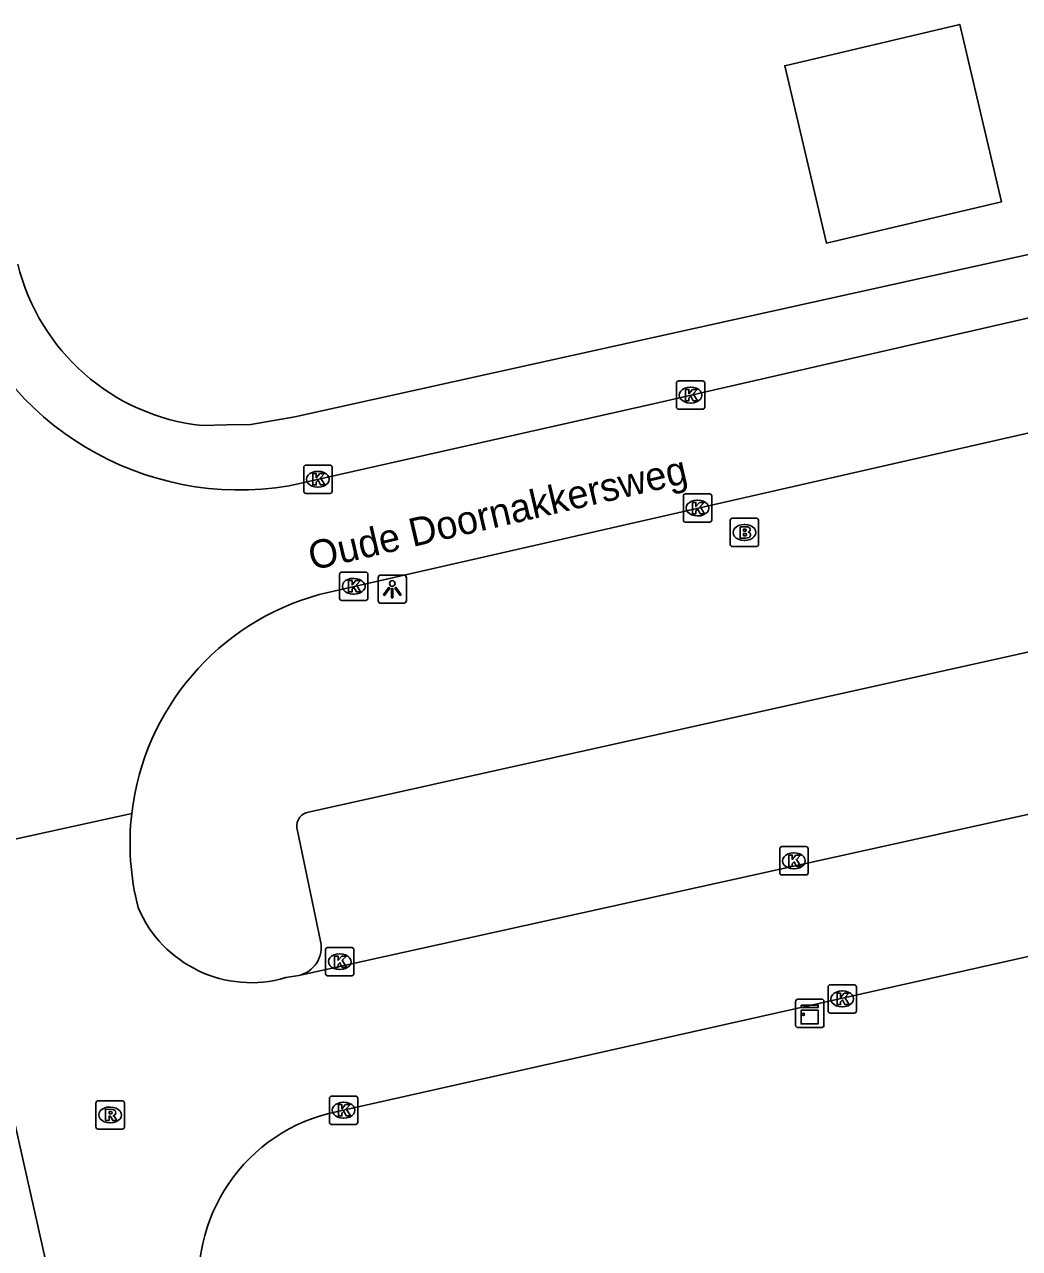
# Model space of a CAD drawing. Extents: x 164494 to 166241, y 382475 to 384494.
# Drawn here: x 164656.08 to 164691.22, y 383419.73 to 383462.97 of the extents above; entities that cross this region are included whole.
import ezdxf

# ---------------------------------------------------------------- set-up
doc = ezdxf.new("R2010")
doc.units = 0
for name, color, linetype in [('IMGEO_Brandkraan', 7, 'Continuous'), ('IMGEO_Groenvoorziening', 7, 'Continuous'), ('IMGEO_Hek', 7, 'Continuous'), ('IMGEO_Kast', 7, 'Continuous'), ('IMGEO_Kolk', 7, 'Continuous'), ('IMGEO_Lichtpunt', 7, 'Continuous'), ('IMGEO_Openbare_ruimte_label', 7, 'Continuous'), ('IMGEO_Pand', 7, 'Continuous'), ('IMGEO_Parkeervlak_open', 7, 'Continuous'), ('IMGEO_Rijbaan_lokaal_open', 7, 'Continuous'), ('IMGEO_Rioolput', 7, 'Continuous')]:
    doc.layers.add(name, color=color, linetype=linetype)

msp = doc.modelspace()

# ---------------------------------------------------------------- linework, layer by layer
at = {"layer": 'IMGEO_Brandkraan'}
for p, q in [((164681.006, 383444.597), (164681.006, 383445.449)), ((164681.081, 383445.523), (164681.933, 383445.523)), ((164681.494, 383445.303), (164681.519, 383445.303)), ((164682.007, 383445.449), (164682.007, 383444.597)), ((164681.517, 383444.743), (164681.492, 383444.743)), ((164681.933, 383444.523), (164681.081, 383444.523))]:
    msp.add_line(p, q, dxfattribs=at)
for points in [[(164681.006, 383444.597), (164681.006, 383445.449)], [(164681.081, 383445.523), (164681.933, 383445.523)], [(164681.354, 383445.223), (164681.354, 383444.823), (164681.567, 383444.823)], [(164681.585, 383445.223), (164681.354, 383445.223)], [(164682.007, 383445.449), (164682.007, 383444.597)], [(164681.533, 383445.142), (164681.479, 383445.142), (164681.479, 383445.066)], [(164681.479, 383445.066), (164681.532, 383445.066)], [(164681.541, 383444.99), (164681.479, 383444.99), (164681.479, 383444.909)], [(164681.479, 383444.909), (164681.541, 383444.909)], [(164681.933, 383444.523), (164681.081, 383444.523)]]:
    msp.add_lwpolyline(points, dxfattribs=at)
for centre, radius, start, end in [((164681.083, 383445.447), 0.0765, 91.552, 178.448), ((164681.083, 383445.447), 0.0765, 91.552, 178.448), ((164681.589, 383445.078), 0.145, 59.4692, 91.5367), ((164681.614, 383445.125), 0.0922, 285.5137, 58.1501), ((164681.931, 383445.447), 0.0765, 1.552, 88.448), ((164681.931, 383445.447), 0.0765, 1.552, 88.448), ((164681.534, 383445.104), 0.0379, 267.8285, 90.9355), ((164681.542, 383444.949), 0.0404, 269.8759, 90.5077), ((164681.573, 383445.074), 0.251, 268.6676, 293.5347), ((164681.619, 383444.933), 0.105, 301.3115, 78.989), ((164681.083, 383444.599), 0.0765, 181.552, 268.448), ((164681.083, 383444.599), 0.0765, 181.552, 268.448), ((164681.931, 383444.599), 0.0765, 271.552, 358.448), ((164681.931, 383444.599), 0.0765, 271.552, 358.448)]:
    msp.add_arc(centre, radius, start, end, dxfattribs=at)
for centre, major_axis, ratio, start_param, end_param in [((164681.493, 383445.023), (-0.387, 0.002), 0.722429, 4.712389, 7.853982), ((164681.518, 383445.023), (-0.39, 0.002), 0.717154, 1.570796, 4.712389)]:
    msp.add_ellipse(centre, major_axis=major_axis, ratio=ratio, start_param=start_param, end_param=end_param, dxfattribs=at)
at = {"layer": 'IMGEO_Groenvoorziening'}
msp.add_lwpolyline([(164662.344, 383448.801), (164663.225, 383448.827), (164664.07, 383448.843), (164665.63, 383449.11), (164723.453, 383461.907)], dxfattribs=at)
msp.add_arc((164663.164, 383456.293), 7.537, 193.7555, 263.7567, dxfattribs=at)
at = {"layer": 'IMGEO_Hek'}
msp.add_arc((164663.164, 383456.293), 7.537, 193.7555, 263.7567, dxfattribs=at)
at = {"layer": 'IMGEO_Kast'}
for p, q in [((164683.314, 383427.61), (164683.314, 383428.451)), ((164683.314, 383428.451), (164683.314, 383427.61)), ((164683.389, 383428.535), (164684.23, 383428.535)), ((164684.23, 383428.535), (164683.389, 383428.535)), ((164684.314, 383428.46), (164684.314, 383427.619)), ((164684.314, 383427.619), (164684.314, 383428.46)), ((164684.239, 383427.535), (164683.398, 383427.535)), ((164683.398, 383427.535), (164684.239, 383427.535))]:
    msp.add_line(p, q, dxfattribs=at)
for points in [[(164683.509, 383428.325), (164684.109, 383428.325), (164684.109, 383428.24), (164683.509, 383428.24), (164683.509, 383428.325)], [(164683.509, 383428.15), (164684.109, 383428.15), (164684.109, 383427.661), (164683.509, 383427.661), (164683.509, 383428.15)]]:
    msp.add_lwpolyline(points, dxfattribs=at)
msp.add_circle((164683.593, 383427.999), 0.0377, dxfattribs=at)
for centre, start, end in [((164683.392, 383428.457), 92.4484, 184.2845), ((164683.392, 383428.457), 92.4484, 184.2845), ((164684.236, 383428.457), 2.4484, 94.2845), ((164684.236, 383428.457), 2.4484, 94.2845), ((164683.392, 383427.613), 182.4484, 274.2845), ((164683.392, 383427.613), 182.4484, 274.2845), ((164684.236, 383427.613), 272.4484, 4.2845), ((164684.236, 383427.613), 272.4484, 4.2845)]:
    msp.add_arc(centre, 0.0779, start, end, dxfattribs=at)
at = {"layer": 'IMGEO_Kolk'}
for p, q in [((164679.179, 383450.376), (164680.031, 383450.376)), ((164679.104, 383449.45), (164679.104, 383450.302)), ((164679.592, 383450.156), (164679.617, 383450.156)), ((164680.105, 383450.302), (164680.105, 383449.45)), ((164679.615, 383449.596), (164679.59, 383449.596)), ((164680.031, 383449.376), (164679.179, 383449.376)), ((164666.015, 383447.402), (164666.867, 383447.402)), ((164665.94, 383446.476), (164665.94, 383447.328)), ((164666.428, 383447.182), (164666.453, 383447.182)), ((164666.941, 383447.328), (164666.941, 383446.476)), ((164666.451, 383446.622), (164666.426, 383446.622)), ((164666.867, 383446.402), (164666.015, 383446.402)), ((164679.349, 383445.461), (164679.349, 383446.313)), ((164679.424, 383446.387), (164680.276, 383446.387)), ((164679.837, 383446.167), (164679.862, 383446.167)), ((164680.35, 383446.313), (164680.35, 383445.461)), ((164679.86, 383445.607), (164679.835, 383445.607)), ((164680.276, 383445.387), (164679.424, 383445.387)), ((164667.207, 383442.695), (164667.207, 383443.547)), ((164667.282, 383443.621), (164668.134, 383443.621)), ((164668.208, 383443.547), (164668.208, 383442.695)), ((164667.695, 383443.401), (164667.72, 383443.401)), ((164668.134, 383442.621), (164667.282, 383442.621)), ((164667.718, 383442.841), (164667.693, 383442.841)), ((164682.753, 383432.997), (164682.753, 383433.849)), ((164682.828, 383433.923), (164683.68, 383433.923)), ((164683.241, 383433.703), (164683.266, 383433.703)), ((164683.754, 383433.849), (164683.754, 383432.997)), ((164683.264, 383433.143), (164683.239, 383433.143)), ((164683.68, 383432.923), (164682.828, 383432.923)), ((164666.711, 383429.434), (164666.711, 383430.286)), ((164666.786, 383430.36), (164667.638, 383430.36)), ((164667.199, 383430.14), (164667.224, 383430.14)), ((164667.712, 383430.286), (164667.712, 383429.434)), ((164667.638, 383429.36), (164666.786, 383429.36)), ((164667.222, 383429.58), (164667.197, 383429.58)), ((164684.46, 383428.119), (164684.46, 383428.971)), ((164684.535, 383429.045), (164685.387, 383429.045)), ((164684.948, 383428.825), (164684.973, 383428.825)), ((164685.461, 383428.971), (164685.461, 383428.119)), ((164685.387, 383428.045), (164684.535, 383428.045)), ((164684.971, 383428.265), (164684.946, 383428.265)), ((164666.848, 383424.186), (164666.848, 383425.038)), ((164666.923, 383425.112), (164667.775, 383425.112)), ((164667.336, 383424.892), (164667.361, 383424.892)), ((164667.849, 383425.038), (164667.849, 383424.186)), ((164667.775, 383424.112), (164666.923, 383424.112)), ((164667.359, 383424.332), (164667.334, 383424.332))]:
    msp.add_line(p, q, dxfattribs=at)
for points in [[(164679.179, 383450.376), (164680.031, 383450.376)], [(164679.104, 383449.45), (164679.104, 383450.302)], [(164679.425, 383450.076), (164679.548, 383450.076), (164679.548, 383449.925), (164679.678, 383450.076), (164679.842, 383450.076), (164679.696, 383449.925), (164679.849, 383449.676), (164679.697, 383449.676), (164679.612, 383449.84), (164679.548, 383449.773), (164679.548, 383449.676), (164679.425, 383449.676), (164679.425, 383450.076)], [(164680.105, 383450.302), (164680.105, 383449.45)], [(164680.031, 383449.376), (164679.179, 383449.376)], [(164666.015, 383447.402), (164666.867, 383447.402)], [(164665.94, 383446.476), (164665.94, 383447.328)], [(164666.261, 383447.102), (164666.384, 383447.102), (164666.384, 383446.951), (164666.514, 383447.102), (164666.678, 383447.102), (164666.532, 383446.951), (164666.685, 383446.702), (164666.533, 383446.702), (164666.448, 383446.866), (164666.384, 383446.799), (164666.384, 383446.702), (164666.261, 383446.702), (164666.261, 383447.102)], [(164666.941, 383447.328), (164666.941, 383446.476)], [(164666.867, 383446.402), (164666.015, 383446.402)], [(164679.349, 383445.461), (164679.349, 383446.313)], [(164679.424, 383446.387), (164680.276, 383446.387)], [(164679.67, 383446.087), (164679.793, 383446.087), (164679.793, 383445.936), (164679.923, 383446.087), (164680.087, 383446.087), (164679.941, 383445.936), (164680.094, 383445.687), (164679.942, 383445.687), (164679.857, 383445.851), (164679.793, 383445.784), (164679.793, 383445.687), (164679.67, 383445.687), (164679.67, 383446.087)], [(164680.35, 383446.313), (164680.35, 383445.461)], [(164680.276, 383445.387), (164679.424, 383445.387)], [(164667.207, 383442.695), (164667.207, 383443.547)], [(164667.282, 383443.621), (164668.134, 383443.621)], [(164668.208, 383443.547), (164668.208, 383442.695)], [(164667.528, 383443.321), (164667.651, 383443.321), (164667.651, 383443.17), (164667.781, 383443.321), (164667.945, 383443.321), (164667.799, 383443.17), (164667.952, 383442.921), (164667.8, 383442.921), (164667.715, 383443.085), (164667.651, 383443.018), (164667.651, 383442.921), (164667.528, 383442.921), (164667.528, 383443.321)], [(164668.134, 383442.621), (164667.282, 383442.621)], [(164682.753, 383432.997), (164682.753, 383433.849)], [(164682.828, 383433.923), (164683.68, 383433.923)], [(164683.074, 383433.623), (164683.197, 383433.623), (164683.197, 383433.472), (164683.327, 383433.623), (164683.491, 383433.623), (164683.345, 383433.472), (164683.498, 383433.223), (164683.346, 383433.223), (164683.261, 383433.387), (164683.197, 383433.32), (164683.197, 383433.223), (164683.074, 383433.223), (164683.074, 383433.623)], [(164683.754, 383433.849), (164683.754, 383432.997)], [(164683.68, 383432.923), (164682.828, 383432.923)], [(164666.711, 383429.434), (164666.711, 383430.286)], [(164666.786, 383430.36), (164667.638, 383430.36)], [(164667.032, 383430.06), (164667.155, 383430.06), (164667.155, 383429.909), (164667.285, 383430.06), (164667.449, 383430.06), (164667.303, 383429.909), (164667.456, 383429.66), (164667.304, 383429.66), (164667.219, 383429.824), (164667.155, 383429.757), (164667.155, 383429.66), (164667.032, 383429.66), (164667.032, 383430.06)], [(164667.712, 383430.286), (164667.712, 383429.434)], [(164667.638, 383429.36), (164666.786, 383429.36)], [(164684.46, 383428.119), (164684.46, 383428.971)], [(164684.535, 383429.045), (164685.387, 383429.045)], [(164684.781, 383428.745), (164684.904, 383428.745), (164684.904, 383428.594), (164685.034, 383428.745), (164685.198, 383428.745), (164685.052, 383428.594), (164685.205, 383428.345), (164685.053, 383428.345), (164684.968, 383428.509), (164684.904, 383428.442), (164684.904, 383428.345), (164684.781, 383428.345), (164684.781, 383428.745)], [(164685.461, 383428.971), (164685.461, 383428.119)], [(164685.387, 383428.045), (164684.535, 383428.045)], [(164666.848, 383424.186), (164666.848, 383425.038)], [(164666.923, 383425.112), (164667.775, 383425.112)], [(164667.849, 383425.038), (164667.849, 383424.186)], [(164667.169, 383424.812), (164667.292, 383424.812), (164667.292, 383424.661), (164667.422, 383424.812), (164667.586, 383424.812), (164667.44, 383424.661), (164667.593, 383424.412), (164667.441, 383424.412), (164667.356, 383424.576), (164667.292, 383424.509), (164667.292, 383424.412), (164667.169, 383424.412), (164667.169, 383424.812)], [(164667.775, 383424.112), (164666.923, 383424.112)]]:
    msp.add_lwpolyline(points, dxfattribs=at)
for centre, start, end in [((164679.181, 383450.3), 91.552, 178.448), ((164679.181, 383450.3), 91.552, 178.448), ((164680.029, 383450.3), 1.552, 88.448), ((164680.029, 383450.3), 1.552, 88.448), ((164679.181, 383449.452), 181.552, 268.448), ((164679.181, 383449.452), 181.552, 268.448), ((164680.029, 383449.452), 271.552, 358.448), ((164680.029, 383449.452), 271.552, 358.448), ((164666.017, 383447.326), 91.552, 178.448), ((164666.017, 383447.326), 91.552, 178.448), ((164666.865, 383447.326), 1.552, 88.448), ((164666.865, 383447.326), 1.552, 88.448), ((164666.017, 383446.478), 181.552, 268.448), ((164666.017, 383446.478), 181.552, 268.448), ((164666.865, 383446.478), 271.552, 358.448), ((164666.865, 383446.478), 271.552, 358.448), ((164679.426, 383446.311), 91.552, 178.448), ((164679.426, 383446.311), 91.552, 178.448), ((164680.274, 383446.311), 1.552, 88.448), ((164680.274, 383446.311), 1.552, 88.448), ((164679.426, 383445.463), 181.552, 268.448), ((164679.426, 383445.463), 181.552, 268.448), ((164680.274, 383445.463), 271.552, 358.448), ((164680.274, 383445.463), 271.552, 358.448), ((164667.284, 383443.545), 91.552, 178.448), ((164667.284, 383443.545), 91.552, 178.448), ((164668.132, 383443.545), 1.552, 88.448), ((164668.132, 383443.545), 1.552, 88.448), ((164667.284, 383442.697), 181.552, 268.448), ((164667.284, 383442.697), 181.552, 268.448), ((164668.132, 383442.697), 271.552, 358.448), ((164668.132, 383442.697), 271.552, 358.448), ((164682.83, 383433.847), 91.552, 178.448), ((164682.83, 383433.847), 91.552, 178.448), ((164683.678, 383433.847), 1.552, 88.448), ((164683.678, 383433.847), 1.552, 88.448), ((164682.83, 383432.999), 181.552, 268.448), ((164682.83, 383432.999), 181.552, 268.448), ((164683.678, 383432.999), 271.552, 358.448), ((164683.678, 383432.999), 271.552, 358.448), ((164666.788, 383430.284), 91.552, 178.448), ((164666.788, 383430.284), 91.552, 178.448), ((164667.636, 383430.284), 1.552, 88.448), ((164667.636, 383430.284), 1.552, 88.448), ((164666.788, 383429.436), 181.552, 268.448), ((164666.788, 383429.436), 181.552, 268.448), ((164667.636, 383429.436), 271.552, 358.448), ((164667.636, 383429.436), 271.552, 358.448), ((164684.537, 383428.969), 91.552, 178.448), ((164684.537, 383428.969), 91.552, 178.448), ((164685.385, 383428.969), 1.552, 88.448), ((164685.385, 383428.969), 1.552, 88.448), ((164684.537, 383428.121), 181.552, 268.448), ((164684.537, 383428.121), 181.552, 268.448), ((164685.385, 383428.121), 271.552, 358.448), ((164685.385, 383428.121), 271.552, 358.448), ((164666.925, 383425.036), 91.552, 178.448), ((164666.925, 383425.036), 91.552, 178.448), ((164667.773, 383425.036), 1.552, 88.448), ((164667.773, 383425.036), 1.552, 88.448), ((164666.925, 383424.188), 181.552, 268.448), ((164666.925, 383424.188), 181.552, 268.448), ((164667.773, 383424.188), 271.552, 358.448), ((164667.773, 383424.188), 271.552, 358.448)]:
    msp.add_arc(centre, 0.0765, start, end, dxfattribs=at)
for centre, major_axis, ratio, start_param, end_param in [((164679.591, 383449.876), (-0.387, 0.002), 0.722429, 4.712389, 7.853982), ((164679.616, 383449.876), (-0.39, 0.002), 0.717154, 1.570796, 4.712389), ((164666.427, 383446.902), (-0.387, 0.002), 0.722429, 4.712389, 7.853982), ((164666.452, 383446.902), (-0.39, 0.002), 0.717154, 1.570796, 4.712389), ((164679.836, 383445.887), (-0.387, 0.002), 0.722429, 4.712389, 7.853982), ((164679.861, 383445.887), (-0.39, 0.002), 0.717154, 1.570796, 4.712389), ((164667.694, 383443.121), (-0.387, 0.002), 0.722429, 4.712389, 7.853982), ((164667.719, 383443.121), (-0.39, 0.002), 0.717154, 1.570796, 4.712389), ((164683.24, 383433.423), (-0.387, 0.002), 0.722429, 4.712389, 7.853982), ((164683.265, 383433.423), (-0.39, 0.002), 0.717154, 1.570796, 4.712389), ((164667.198, 383429.86), (-0.387, 0.002), 0.722429, 4.712389, 7.853982), ((164667.223, 383429.86), (-0.39, 0.002), 0.717154, 1.570796, 4.712389), ((164684.947, 383428.545), (-0.387, 0.002), 0.722429, 4.712389, 7.853982), ((164684.972, 383428.545), (-0.39, 0.002), 0.717154, 1.570796, 4.712389), ((164667.335, 383424.612), (-0.387, 0.002), 0.722429, 4.712389, 7.853982), ((164667.36, 383424.612), (-0.39, 0.002), 0.717154, 1.570796, 4.712389)]:
    msp.add_ellipse(centre, major_axis=major_axis, ratio=ratio, start_param=start_param, end_param=end_param, dxfattribs=at)
at = {"layer": 'IMGEO_Lichtpunt'}
for p, q in [((164669.472, 383443.519), (164668.664, 383443.519)), ((164669.472, 383443.519), (164668.664, 383443.519)), ((164668.57, 383443.424), (164668.57, 383442.617)), ((164668.57, 383443.424), (164668.57, 383442.617)), ((164669.566, 383442.617), (164669.566, 383443.424)), ((164669.566, 383442.617), (164669.566, 383443.424)), ((164668.664, 383442.523), (164669.472, 383442.523)), ((164668.664, 383442.523), (164669.472, 383442.523))]:
    msp.add_line(p, q, dxfattribs=at)
for points in [[(164668.944, 383443.088), (164668.983, 383443.06), (164668.795, 383442.798), (164668.757, 383442.825), (164668.944, 383443.088)], [(164669.046, 383443.04), (164669.093, 383443.04), (164669.093, 383442.718), (164669.046, 383442.718), (164669.046, 383443.04)], [(164669.156, 383443.06), (164669.194, 383443.087), (164669.381, 383442.825), (164669.342, 383442.797), (164669.156, 383443.06)]]:
    msp.add_lwpolyline(points, dxfattribs=at)
msp.add_circle((164669.069, 383443.222), 0.0994, dxfattribs=at)
for centre, start, end in [((164668.664, 383443.424), 90, 180), ((164668.664, 383443.424), 90, 180), ((164669.472, 383443.424), 0, 90), ((164669.472, 383443.424), 0, 90), ((164668.664, 383442.617), 180, 270), ((164668.664, 383442.617), 180, 270), ((164669.472, 383442.617), 270, 0), ((164669.472, 383442.617), 270, 360)]:
    msp.add_arc(centre, 0.0946, start, end, dxfattribs=at)
at = {"layer": 'IMGEO_Pand'}
msp.add_lwpolyline([(164690.59, 383456.706), (164684.41, 383455.247), (164682.931, 383461.51), (164689.111, 383462.969), (164690.59, 383456.706)], dxfattribs=at)
at = {"layer": 'IMGEO_Parkeervlak_open'}
for points in [[(164701.141, 383442.934), (164666.11, 383435.14)], [(164665.713, 383434.537), (164666.536, 383430.582)]]:
    msp.add_lwpolyline(points, dxfattribs=at)
for centre, radius, start, end in [((164666.182, 383434.66), 0.485, 98.564, 194.7162), ((164665.533, 383430.369), 1.025, 283.1335, 11.9669)]:
    msp.add_arc(centre, radius, start, end, dxfattribs=at)
at = {"layer": 'IMGEO_Rijbaan_lokaal_open'}
for points in [[(164719.895, 383459.238), (164717.739, 383458.983), (164712.427, 383457.585), (164708.916, 383456.753), (164693.004, 383452.936), (164678.342, 383449.582), (164665.421, 383446.666)], [(164696.172, 383449.592), (164666.487, 383442.83)], [(164665.766, 383429.371), (164703.825, 383437.779)], [(164659.867, 383435.096), (164653.262, 383433.646)], [(164657.598, 383415.827), (164656.836, 383419.271), (164654.781, 383428.342), (164653.876, 383432.334), (164653.262, 383433.646)], [(164704.167, 383432.878), (164667.135, 383424.569)], [(164665.766, 383429.371), (164665.311, 383429.296)]]:
    msp.add_lwpolyline(points, dxfattribs=at)
for centre, radius, start, end in [((164663.684, 383457.099), 10.576, 198.5047, 279.4548), ((164668.92, 383434.047), 9.114, 105.4856, 173.39), ((164668.91, 383434.044), 9.104, 173.3642, 194.4243), ((164664.086, 383433.448), 4.329, 202.7182, 286.4403), ((164668.331, 383418.591), 6.097, 101.3178, 190.1851)]:
    msp.add_arc(centre, radius, start, end, dxfattribs=at)
at = {"layer": 'IMGEO_Rioolput'}
for p, q in [((164658.604, 383424.018), (164658.604, 383424.87)), ((164658.679, 383424.944), (164659.531, 383424.944)), ((164659.605, 383424.87), (164659.605, 383424.018)), ((164659.092, 383424.724), (164659.117, 383424.724)), ((164659.115, 383424.164), (164659.09, 383424.164)), ((164659.531, 383423.944), (164658.679, 383423.944))]:
    msp.add_line(p, q, dxfattribs=at)
for points in [[(164658.604, 383424.018), (164658.604, 383424.87)], [(164658.679, 383424.944), (164659.531, 383424.944)], [(164659.605, 383424.87), (164659.605, 383424.018)], [(164659.193, 383424.642), (164658.941, 383424.644), (164658.941, 383424.244)], [(164659.119, 383424.563), (164659.065, 383424.563), (164659.065, 383424.482)], [(164659.065, 383424.482), (164659.117, 383424.482)], [(164658.941, 383424.244), (164659.065, 383424.244), (164659.065, 383424.406), (164659.076, 383424.406)], [(164659.123, 383424.377), (164659.194, 383424.244), (164659.334, 383424.244), (164659.269, 383424.37)], [(164659.531, 383423.944), (164658.679, 383423.944)]]:
    msp.add_lwpolyline(points, dxfattribs=at)
for centre, radius, start, end in [((164658.681, 383424.868), 0.0765, 91.552, 178.448), ((164658.681, 383424.868), 0.0765, 91.552, 178.448), ((164659.529, 383424.868), 0.0765, 1.552, 88.448), ((164659.529, 383424.868), 0.0765, 1.552, 88.448), ((164659.101, 383424.671), 0.19, 274.7715, 282.9687), ((164659.125, 383424.467), 0.0964, 77.0061, 93.1865), ((164659.139, 383424.524), 0.0378, 276.6634, 79.6772), ((164659.192, 383424.532), 0.109, 350.3612, 89.416), ((164659.19, 383424.532), 0.112, 277.5842, 350.9817), ((164659.174, 383424.317), 0.108, 29.5134, 73.7905), ((164658.681, 383424.02), 0.0765, 181.552, 268.448), ((164658.681, 383424.02), 0.0765, 181.552, 268.448), ((164659.075, 383424.353), 0.0533, 26.0293, 88.6989), ((164659.529, 383424.02), 0.0765, 271.552, 358.448), ((164659.529, 383424.02), 0.0765, 271.552, 358.448)]:
    msp.add_arc(centre, radius, start, end, dxfattribs=at)
for centre, major_axis, ratio, start_param, end_param in [((164659.091, 383424.444), (-0.387, 0.002), 0.722429, 4.712389, 7.853982), ((164659.116, 383424.444), (-0.39, 0.002), 0.717154, 1.570796, 4.712389)]:
    msp.add_ellipse(centre, major_axis=major_axis, ratio=ratio, start_param=start_param, end_param=end_param, dxfattribs=at)

# ---------------------------------------------------------------- texts
at = {"layer": 'IMGEO_Openbare_ruimte_label'}
msp.add_text('Oude Doornakkersweg', height=1, rotation=13.1191, dxfattribs=at).set_placement((164666.24, 383443.68))

doc.saveas('drawing.dxf')
